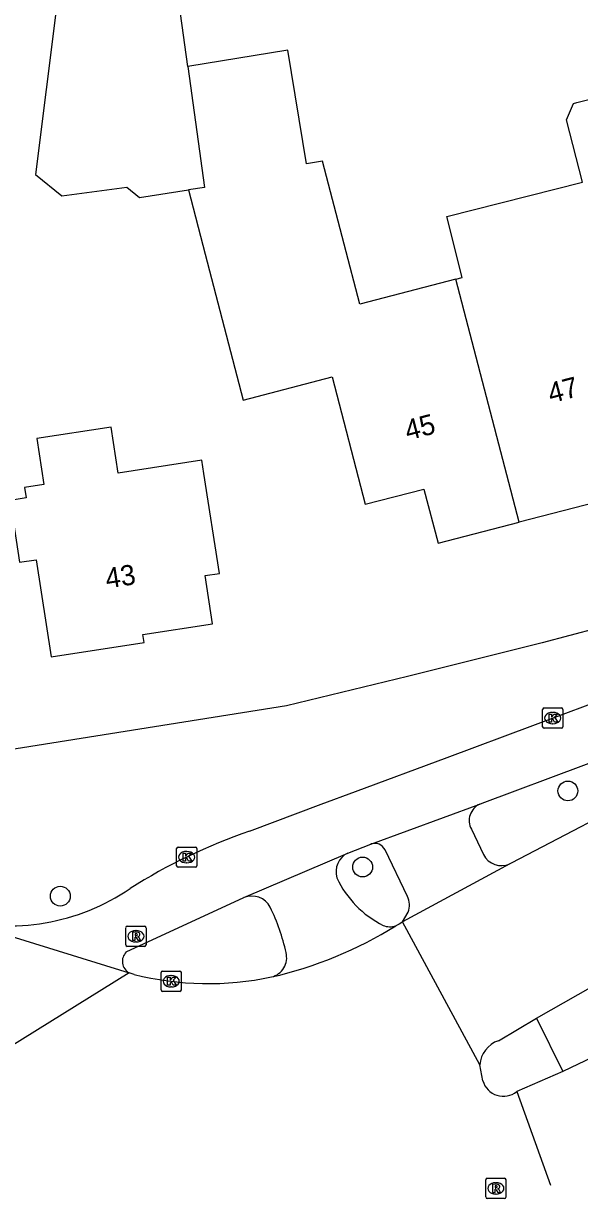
# Model space of a CAD drawing. Extents: x 161354 to 161876, y 382161 to 382804.
# Drawn here: x 161749.1 to 161776.5, y 382278.1 to 382336.2 of the extents above; entities that cross this region are included whole.
import ezdxf

# ---------------------------------------------------------------- set-up
doc = ezdxf.new("R2010")
doc.units = 0
for name, color, linetype in [('IMGEO_Boom', 7, 'Continuous'), ('IMGEO_Fietspad_open', 7, 'Continuous'), ('IMGEO_Kolk', 7, 'Continuous'), ('IMGEO_Pand', 7, 'Continuous'), ('IMGEO_Pand_nummerreeks', 7, 'Continuous'), ('IMGEO_Rijbaan_lokaal_gesloten', 7, 'Continuous'), ('IMGEO_Rioolput', 7, 'Continuous'), ('IMGEO_Verkeerseiland_open', 7, 'Continuous'), ('IMGEO_Voetpad_open', 7, 'Continuous')]:
    doc.layers.add(name, color=color, linetype=linetype)

msp = doc.modelspace()

# ---------------------------------------------------------------- linework, layer by layer
at = {"layer": 'IMGEO_Boom'}
for centre in [(161775.953, 382298.261), (161765.815, 382294.5), (161750.878, 382293.059)]:
    msp.add_circle(centre, 0.489, dxfattribs=at)
at = {"layer": 'IMGEO_Fietspad_open'}
for points in [[(161760.23, 382296.278), (161763.762, 382297.602), (161765.459, 382298.241), (161769.989, 382299.908), (161782.68, 382304.663), (161786.203, 382305.955), (161787.709, 382306.524), (161794.858, 382309.544)], [(161771.607, 382297.615), (161771.727, 382297.659), (161781.757, 382301.412)], [(161766.226, 382295.638), (161771.607, 382297.615)], [(161765.083, 382295.192), (161766.226, 382295.638)], [(161759.95, 382292.993), (161765.083, 382295.192)], [(161754.137, 382290.3), (161759.95, 382292.993)]]:
    msp.add_lwpolyline(points, dxfattribs=at)
for centre, radius, start, end in [((161769.474, 382269.523), 28.307, 109.06111, 122.35647), ((161748.345, 382302.186), 10.599, 255.02337, 304.34641), ((161754.591, 382289.838), 0.648, 134.50535, 242.00302)]:
    msp.add_arc(centre, radius, start, end, dxfattribs=at)
at = {"layer": 'IMGEO_Kolk'}
for p, q in [((161774.78, 382302.364), (161775.632, 382302.364)), ((161774.705, 382301.438), (161774.705, 382302.29)), ((161775.193, 382302.144), (161775.218, 382302.144)), ((161775.706, 382302.29), (161775.706, 382301.438)), ((161775.632, 382301.364), (161774.78, 382301.364)), ((161775.216, 382301.584), (161775.191, 382301.584)), ((161756.623, 382294.563), (161756.623, 382295.415)), ((161756.698, 382295.489), (161757.55, 382295.489)), ((161757.624, 382295.415), (161757.624, 382294.563)), ((161757.111, 382295.269), (161757.136, 382295.269)), ((161757.55, 382294.489), (161756.698, 382294.489)), ((161757.134, 382294.709), (161757.109, 382294.709)), ((161755.856, 382288.428), (161755.856, 382289.28)), ((161755.931, 382289.354), (161756.783, 382289.354)), ((161756.344, 382289.134), (161756.369, 382289.134)), ((161756.857, 382289.28), (161756.857, 382288.428)), ((161756.367, 382288.574), (161756.342, 382288.574)), ((161756.783, 382288.354), (161755.931, 382288.354))]:
    msp.add_line(p, q, dxfattribs=at)
for points in [[(161774.78, 382302.364), (161775.632, 382302.364)], [(161774.705, 382301.438), (161774.705, 382302.29)], [(161775.026, 382302.064), (161775.149, 382302.064), (161775.149, 382301.913), (161775.279, 382302.064), (161775.443, 382302.064), (161775.297, 382301.913), (161775.45, 382301.664), (161775.298, 382301.664), (161775.213, 382301.828), (161775.149, 382301.761), (161775.149, 382301.664), (161775.026, 382301.664), (161775.026, 382302.064)], [(161775.706, 382302.29), (161775.706, 382301.438)], [(161775.632, 382301.364), (161774.78, 382301.364)], [(161756.623, 382294.563), (161756.623, 382295.415)], [(161756.698, 382295.489), (161757.55, 382295.489)], [(161757.624, 382295.415), (161757.624, 382294.563)], [(161756.944, 382295.189), (161757.067, 382295.189), (161757.067, 382295.038), (161757.197, 382295.189), (161757.361, 382295.189), (161757.215, 382295.038), (161757.368, 382294.789), (161757.216, 382294.789), (161757.131, 382294.953), (161757.067, 382294.886), (161757.067, 382294.789), (161756.944, 382294.789), (161756.944, 382295.189)], [(161757.55, 382294.489), (161756.698, 382294.489)], [(161755.856, 382288.428), (161755.856, 382289.28)], [(161755.931, 382289.354), (161756.783, 382289.354)], [(161756.177, 382289.054), (161756.3, 382289.054), (161756.3, 382288.903), (161756.43, 382289.054), (161756.594, 382289.054), (161756.448, 382288.903), (161756.601, 382288.654), (161756.449, 382288.654), (161756.364, 382288.818), (161756.3, 382288.751), (161756.3, 382288.654), (161756.177, 382288.654), (161756.177, 382289.054)], [(161756.857, 382289.28), (161756.857, 382288.428)], [(161756.783, 382288.354), (161755.931, 382288.354)]]:
    msp.add_lwpolyline(points, dxfattribs=at)
for centre, start, end in [((161774.782, 382302.288), 91.55205, 178.44795), ((161774.782, 382302.288), 91.55205, 178.44795), ((161775.63, 382302.288), 1.55205, 88.44795), ((161775.63, 382302.288), 1.55205, 88.44795), ((161774.782, 382301.44), 181.55205, 268.44795), ((161774.782, 382301.44), 181.55205, 268.44795), ((161775.63, 382301.44), 271.55205, 358.44795), ((161775.63, 382301.44), 271.55205, 358.44795), ((161756.7, 382295.413), 91.55205, 178.44795), ((161756.7, 382295.413), 91.55205, 178.44795), ((161757.548, 382295.413), 1.55205, 88.44795), ((161757.548, 382295.413), 1.55205, 88.44795), ((161756.7, 382294.565), 181.55205, 268.44795), ((161756.7, 382294.565), 181.55205, 268.44795), ((161757.548, 382294.565), 271.55205, 358.44795), ((161757.548, 382294.565), 271.55205, 358.44795), ((161755.933, 382289.278), 91.55205, 178.44795), ((161755.933, 382289.278), 91.55205, 178.44795), ((161756.781, 382289.278), 1.55205, 88.44795), ((161756.781, 382289.278), 1.55205, 88.44795), ((161755.933, 382288.43), 181.55205, 268.44795), ((161755.933, 382288.43), 181.55205, 268.44795), ((161756.781, 382288.43), 271.55205, 358.44795), ((161756.781, 382288.43), 271.55205, 358.44795)]:
    msp.add_arc(centre, 0.0765, start, end, dxfattribs=at)
for centre, major_axis, ratio, start_param, end_param in [((161775.192, 382301.864), (-0.387, 0.002), 0.722429, 4.712389, 7.853982), ((161775.217, 382301.864), (-0.39, 0.002), 0.717154, 1.570796, 4.712389), ((161757.11, 382294.989), (-0.387, 0.002), 0.722429, 4.712389, 7.853982), ((161757.135, 382294.989), (-0.39, 0.002), 0.717154, 1.570796, 4.712389), ((161756.343, 382288.854), (-0.387, 0.002), 0.722429, 4.712389, 7.853982), ((161756.368, 382288.854), (-0.39, 0.002), 0.717154, 1.570796, 4.712389)]:
    msp.add_ellipse(centre, major_axis=major_axis, ratio=ratio, start_param=start_param, end_param=end_param, dxfattribs=at)
at = {"layer": 'IMGEO_Pand'}
for points in [[(161757.18, 382334.07), (161756.089, 382341.947), (161751.257, 382341.482), (161749.648, 382328.729), (161750.952, 382327.686), (161754.159, 382328.104), (161754.796, 382327.594), (161757.211, 382327.971)], [(161770.422, 382323.558), (161765.672, 382322.325), (161764.903, 382325.286), (161763.837, 382329.391), (161763.042, 382329.26), (161762.113, 382334.884), (161757.18, 382334.07)], [(161757.18, 382334.07), (161758.008, 382328.095), (161757.211, 382327.971)], [(161770.422, 382323.558), (161770.735, 382323.639), (161769.97, 382326.652), (161776.676, 382328.355), (161775.893, 382331.437), (161776.234, 382332.246), (161776.39, 382332.286), (161781.236, 382333.517)], [(161757.211, 382327.971), (161758.035, 382324.795), (161759.905, 382317.583), (161764.309, 382318.725), (161765.941, 382312.433), (161768.844, 382313.186), (161769.539, 382310.504), (161773.549, 382311.545)], [(161773.549, 382311.545), (161770.422, 382323.558)], [(161783.907, 382323.372), (161778.545, 382322.016), (161780.079, 382316.102), (161777.194, 382315.353), (161777.889, 382312.671), (161773.549, 382311.545)], [(161748.395, 382312.614), (161748.865, 382309.565), (161749.686, 382309.692), (161750.425, 382304.894), (161755.015, 382305.601), (161754.956, 382305.987), (161758.404, 382306.518), (161758.037, 382308.906), (161758.735, 382309.013), (161757.975, 382313.955), (161757.874, 382314.613), (161753.737, 382313.977), (161753.388, 382316.245), (161749.721, 382315.681), (161750.071, 382313.413), (161749.109, 382313.265), (161749.188, 382312.754), (161748.395, 382312.614)]]:
    msp.add_lwpolyline(points, dxfattribs=at)
at = {"layer": 'IMGEO_Rijbaan_lokaal_gesloten'}
for points in [[(161782.565, 382299.495), (161781.439, 382298.98), (161780.32, 382298.423), (161773.187, 382294.715), (161773.084, 382294.659)], [(161773.084, 382294.659), (161767.783, 382291.787)], [(161745.606, 382291.947), (161754.287, 382289.266)], [(161767.783, 382291.787), (161767.697, 382291.732), (161767.612, 382291.679), (161767.449, 382291.592)], [(161771.609, 382284.717), (161767.783, 382291.787)], [(161754.287, 382289.266), (161745.072, 382283.557)], [(161754.519, 382289.194), (161754.287, 382289.266)], [(161774.402, 382287.033), (161778.525, 382289.374)], [(161772.518, 382285.914), (161774.402, 382287.033)], [(161778.675, 382285.81), (161775.696, 382284.397)], [(161771.754, 382283.931), (161771.609, 382284.717)], [(161775.696, 382284.397), (161773.427, 382283.398)], [(161773.427, 382283.398), (161775.102, 382278.769)]]:
    msp.add_lwpolyline(points, dxfattribs=at)
for centre, radius, start, end in [((161756.855, 382308.597), 20.035, 282.86461, 301.92198), ((161758.196, 382303.8), 15.061, 255.8697, 281.95573), ((161772.954, 382284.639), 1.347, 108.87866, 176.69537), ((161772.766, 382284.214), 1.05, 195.62338, 309.03397)]:
    msp.add_arc(centre, radius, start, end, dxfattribs=at)
at = {"layer": 'IMGEO_Rioolput'}
for p, q in [((161754.112, 382290.65), (161754.112, 382291.502)), ((161754.187, 382291.576), (161755.039, 382291.576)), ((161754.6, 382291.356), (161754.625, 382291.356)), ((161755.113, 382291.502), (161755.113, 382290.65)), ((161754.623, 382290.796), (161754.598, 382290.796)), ((161755.039, 382290.576), (161754.187, 382290.576)), ((161771.97, 382279.114), (161772.822, 382279.114)), ((161771.895, 382278.188), (161771.895, 382279.04)), ((161772.383, 382278.894), (161772.408, 382278.894)), ((161772.896, 382279.04), (161772.896, 382278.188)), ((161772.822, 382278.114), (161771.97, 382278.114)), ((161772.406, 382278.334), (161772.381, 382278.334))]:
    msp.add_line(p, q, dxfattribs=at)
for points in [[(161754.112, 382290.65), (161754.112, 382291.502)], [(161754.187, 382291.576), (161755.039, 382291.576)], [(161755.113, 382291.502), (161755.113, 382290.65)], [(161754.701, 382291.274), (161754.449, 382291.276), (161754.449, 382290.876)], [(161754.449, 382290.876), (161754.573, 382290.876), (161754.573, 382291.038), (161754.584, 382291.038)], [(161754.627, 382291.195), (161754.573, 382291.195), (161754.573, 382291.114)], [(161754.573, 382291.114), (161754.625, 382291.114)], [(161754.631, 382291.009), (161754.702, 382290.876), (161754.842, 382290.876), (161754.777, 382291.002)], [(161755.039, 382290.576), (161754.187, 382290.576)], [(161771.97, 382279.114), (161772.822, 382279.114)], [(161771.895, 382278.188), (161771.895, 382279.04)], [(161772.484, 382278.812), (161772.232, 382278.814), (161772.232, 382278.414)], [(161772.232, 382278.414), (161772.356, 382278.414), (161772.356, 382278.576), (161772.367, 382278.576)], [(161772.41, 382278.733), (161772.356, 382278.733), (161772.356, 382278.652)], [(161772.356, 382278.652), (161772.408, 382278.652)], [(161772.414, 382278.547), (161772.485, 382278.414), (161772.625, 382278.414), (161772.56, 382278.54)], [(161772.896, 382279.04), (161772.896, 382278.188)], [(161772.822, 382278.114), (161771.97, 382278.114)]]:
    msp.add_lwpolyline(points, dxfattribs=at)
for centre, radius, start, end in [((161754.189, 382291.5), 0.0765, 91.55205, 178.44795), ((161754.189, 382291.5), 0.0765, 91.55205, 178.44795), ((161755.037, 382291.5), 0.0765, 1.55205, 88.44795), ((161755.037, 382291.5), 0.0765, 1.55205, 88.44795), ((161754.583, 382290.985), 0.0533, 26.02933, 88.69889), ((161754.609, 382291.303), 0.19, 274.7715, 282.96867), ((161754.633, 382291.099), 0.0964, 77.00612, 93.18647), ((161754.647, 382291.156), 0.0378, 276.66336, 79.67722), ((161754.7, 382291.164), 0.109, 350.36119, 89.41601), ((161754.698, 382291.164), 0.112, 277.58423, 350.98172), ((161754.682, 382290.949), 0.108, 29.51342, 73.79051), ((161754.189, 382290.652), 0.0765, 181.55205, 268.44795), ((161754.189, 382290.652), 0.0765, 181.55205, 268.44795), ((161755.037, 382290.652), 0.0765, 271.55205, 358.44795), ((161755.037, 382290.652), 0.0765, 271.55205, 358.44795), ((161771.972, 382279.038), 0.0765, 91.55205, 178.44795), ((161771.972, 382279.038), 0.0765, 91.55205, 178.44795), ((161772.82, 382279.038), 0.0765, 1.55205, 88.44795), ((161772.82, 382279.038), 0.0765, 1.55205, 88.44795), ((161772.366, 382278.523), 0.0533, 26.02933, 88.69889), ((161772.392, 382278.841), 0.19, 274.7715, 282.96867), ((161772.416, 382278.637), 0.0964, 77.00612, 93.18647), ((161772.43, 382278.694), 0.0378, 276.66336, 79.67722), ((161772.483, 382278.702), 0.109, 350.36119, 89.41601), ((161772.481, 382278.702), 0.112, 277.58423, 350.98172), ((161772.465, 382278.487), 0.108, 29.51342, 73.79051), ((161771.972, 382278.19), 0.0765, 181.55205, 268.44795), ((161771.972, 382278.19), 0.0765, 181.55205, 268.44795), ((161772.82, 382278.19), 0.0765, 271.55205, 358.44795), ((161772.82, 382278.19), 0.0765, 271.55205, 358.44795)]:
    msp.add_arc(centre, radius, start, end, dxfattribs=at)
for centre, major_axis, ratio, start_param, end_param in [((161754.599, 382291.076), (-0.387, 0.002), 0.722429, 4.712389, 7.853982), ((161754.624, 382291.076), (-0.39, 0.002), 0.717154, 1.570796, 4.712389), ((161772.382, 382278.614), (-0.387, 0.002), 0.722429, 4.712389, 7.853982), ((161772.407, 382278.614), (-0.39, 0.002), 0.717154, 1.570796, 4.712389)]:
    msp.add_ellipse(centre, major_axis=major_axis, ratio=ratio, start_param=start_param, end_param=end_param, dxfattribs=at)
at = {"layer": 'IMGEO_Verkeerseiland_open'}
msp.add_lwpolyline([(161774.402, 382287.033), (161775.696, 382284.397)], dxfattribs=at)
at = {"layer": 'IMGEO_Voetpad_open'}
for points in [[(161786.77, 382309.433), (161785.539, 382308.875), (161785.615, 382308.486), (161774.681, 382305.586), (161768.027, 382303.924), (161762.045, 382302.471), (161747.542, 382300.159)], [(161771.184, 382296.368), (161771.789, 382295.116)], [(161768.027, 382293.05), (161766.921, 382295.346)], [(161767.783, 382291.787), (161768.062, 382292.276)]]:
    msp.add_lwpolyline(points, dxfattribs=at)
for centre, radius, start, end in [((161771.975, 382296.795), 0.899, 114.18241, 208.34227), ((161766.409, 382295.101), 0.568, 25.60719, 108.81398), ((161765.531, 382294.26), 1.035, 115.67014, 196.65601), ((161772.669, 382295.548), 0.981, 206.11525, 295.00931), ((161769.085, 382296.098), 5.022, 205.15644, 243.26172), ((161760.332, 382292.035), 1.032, 27.24984, 111.7251), ((161767.143, 382292.622), 0.982, 339.36678, 25.81148), ((161752.372, 382288.157), 9.886, 12.3197, 26.10772), ((161767.167, 382292.466), 0.918, 248.22541, 287.91341), ((161761.077, 382290.02), 0.985, 284.07148, 14.46516)]:
    msp.add_arc(centre, radius, start, end, dxfattribs=at)

# ---------------------------------------------------------------- texts
at = {"layer": 'IMGEO_Pand_nummerreeks'}
for s, rotation, p in [('47', 14.5481, (161775.112, 382317.417)), ('45', 14.5481, (161768.043, 382315.582)), ('43', 8.7549, (161753.184, 382308.264))]:
    msp.add_text(s, height=1, rotation=rotation, dxfattribs=at).set_placement(p)

doc.saveas('drawing.dxf')
